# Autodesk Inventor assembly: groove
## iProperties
Created: 2005-03
Part Number: groove
Document SubType Name: Weldment
Designer: CADCIM
Manufacturer: Standard
Standards Organization: Custom
Author: CADCIM
